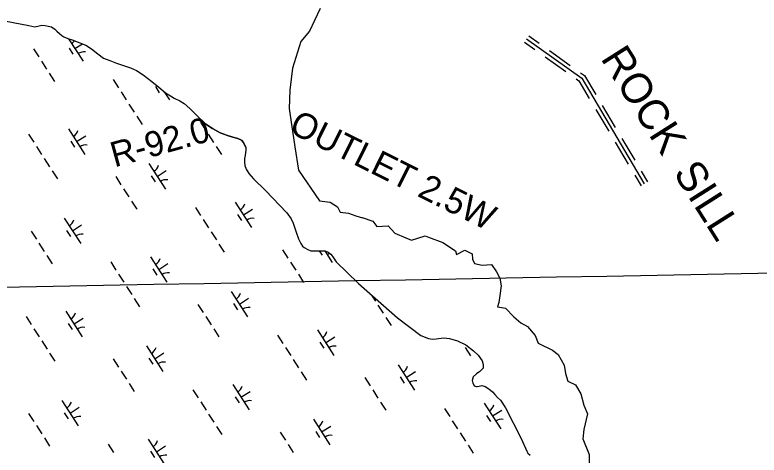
# Model space of a CAD drawing. Extents: x 3937982 to 3958556, y 219448 to 241894.
# Drawn here: x 3947179 to 3948409, y 230057 to 230784 of the extents above; entities that cross this region are included whole.
import ezdxf

# ---------------------------------------------------------------- set-up
doc = ezdxf.new("R2010")
doc.units = 0
for name, color, linetype in [('V-GRID-MAJR', 7, 'Continuous'), ('V-RIVR-EDGE', 7, 'Continuous'), ('V-RIVR-RANG-IDEN', 7, 'Continuous'), ('V-RRAP-DIKE', 7, 'Continuous'), ('V-RRAP-SILL-IDEN', 7, 'Continuous'), ('V-TOPO-SHOR', 7, 'Continuous'), ('V-WETL-SWMP', 7, 'Continuous')]:
    doc.layers.add(name, color=color, linetype=linetype)

msp = doc.modelspace()

# ---------------------------------------------------------------- linework, layer by layer
at = {"layer": 'V-GRID-MAJR'}
msp.add_spline([(3944087.88, 230278.368), (3946078.329, 230314.506), (3951399.696, 230411.652), (3955204.154, 230481.575)], degree=3, dxfattribs=at)
at = {"layer": 'V-RIVR-EDGE'}
for points in [[(3947683.499, 230794.294), (3947673.728, 230774.175), (3947665.68, 230756.931), (3947651.31, 230739.687), (3947637.514, 230695.426), (3947633.491, 230659.213), (3947632.341, 230628.748), (3947635.79, 230602.306), (3947641.538, 230565.518), (3947647.286, 230527.005), (3947682.062, 230476.709), (3947699.882, 230474.41), (3947711.953, 230466.363), (3947716.551, 230457.74), (3947730.347, 230456.016), (3947742.418, 230451.992), (3947753.196, 230448.687)], [(3947753.018, 230448.728), (3947770.118, 230443.028), (3947776.998, 230434.181), (3947795.673, 230435.164), (3947806.485, 230423.37), (3947825.16, 230415.506), (3947834.006, 230411.575), (3947856.613, 230418.455), (3947862.51, 230416.489), (3947886.1, 230407.643), (3947906.741, 230393.883), (3947908.706, 230387.985), (3947922.467, 230394.866), (3947934.262, 230388.968), (3947935.245, 230380.122), (3947938.193, 230373.242), (3947950.971, 230370.293), (3947966.697, 230371.276), (3947974.56, 230359.481), (3947980.458, 230348.67), (3947982.424, 230335.892), (3947980.458, 230320.166), (3947978.492, 230308.371), (3947976.526, 230301.491), (3947989.304, 230299.525), (3948003.064, 230284.781), (3948014.859, 230274.952), (3948025.671, 230269.055), (3948038.449, 230254.312), (3948043.363, 230241.534), (3948066.953, 230229.739), (3948076.782, 230222.859), (3948086.611, 230205.167), (3948088.576, 230191.406), (3948092.508, 230178.629), (3948105.286, 230172.731), (3948114.132, 230157.988), (3948119.046, 230139.313), (3948124.944, 230124.569), (3948119.046, 230099.014), (3948117.08, 230083.288), (3948127.892, 230057.732), (3948127.892, 230037.092)]]:
    msp.add_lwpolyline(points, dxfattribs=at)
at = {"layer": 'V-RRAP-DIKE'}
for points in [[(3948024.37, 230743.746), (3948115.495, 230678.973), (3948218.84, 230504.57)], [(3948027.991, 230748.84), (3948045.107, 230736.674)], [(3948020.749, 230738.652), (3948037.865, 230726.486)], [(3948062.223, 230724.507), (3948096.456, 230700.174)], [(3948054.981, 230714.319), (3948089.214, 230689.986)], [(3948113.572, 230688.008), (3948120.196, 230683.3), (3948138.816, 230651.878)], [(3948106.33, 230677.818), (3948110.794, 230674.646), (3948128.062, 230645.506)], [(3948149.521, 230633.812), (3948170.932, 230597.679)], [(3948138.767, 230627.44), (3948160.178, 230591.307)], [(3948170.883, 230573.241), (3948192.294, 230537.108)], [(3948181.637, 230579.613), (3948203.048, 230543.48)], [(3948213.754, 230525.414), (3948224.217, 230507.756)], [(3948203, 230519.042), (3948213.463, 230501.384)]]:
    msp.add_lwpolyline(points, dxfattribs=at)
at = {"layer": 'V-TOPO-SHOR'}
for p, q in [((3947139.6, 230778.041), (3947201.951, 230765.854)), ((3947201.951, 230765.854), (3947211.757, 230764.089)), ((3947219.203, 230765.329), (3947223.388, 230766.304)), ((3947223.388, 230766.304), (3947228.983, 230766.127)), ((3947228.983, 230766.127), (3947234.122, 230765.014)), ((3947211.757, 230764.089), (3947219.203, 230765.329)), ((3947234.122, 230765.014), (3947239.496, 230763.67)), ((3947239.496, 230763.67), (3947245.129, 230759.765)), ((3947245.129, 230759.765), (3947248.425, 230756.536)), ((3947248.425, 230756.536), (3947252.892, 230752.619)), ((3947252.892, 230752.619), (3947256.419, 230749.625)), ((3947256.419, 230749.625), (3947259.94, 230747.097)), ((3947259.94, 230747.097), (3947266.491, 230744.599)), ((3947266.491, 230744.599), (3947273.741, 230742.109)), ((3947273.741, 230742.109), (3947286.372, 230737.576)), ((3947286.372, 230737.576), (3947296.203, 230733.48)), ((3947296.203, 230733.48), (3947305.588, 230727.282)), ((3947305.588, 230727.282), (3947315.922, 230719.463)), ((3947315.922, 230719.463), (3947325.316, 230712.333)), ((3947325.316, 230712.333), (3947336.081, 230708.014)), ((3947336.081, 230708.014), (3947347.076, 230703.93)), ((3947347.076, 230703.93), (3947358.537, 230699.851)), ((3947358.537, 230699.851), (3947370.229, 230696.007)), ((3947370.229, 230696.007), (3947380.059, 230691.912)), ((3947380.059, 230691.912), (3947391.085, 230684.798)), ((3947391.085, 230684.798), (3947405.416, 230673.523)), ((3947405.416, 230673.523), (3947416.696, 230664.315)), ((3947416.696, 230664.315), (3947427.746, 230654.871)), ((3947427.746, 230654.871), (3947435.954, 230649.827)), ((3947435.954, 230649.827), (3947442.284, 230646.162)), ((3947442.284, 230646.162), (3947451.653, 230641.596)), ((3947451.653, 230641.596), (3947458.691, 230637.006))]:
    msp.add_line(p, q, dxfattribs=at)
msp.add_lwpolyline([(3947560.579, 230564.525), (3947556.759, 230572.973), (3947553.226, 230576.665), (3947547.371, 230579.403), (3947539.189, 230581.886), (3947530.307, 230584.36), (3947518.376, 230588.898), (3947505.488, 230595.761), (3947494.692, 230603.109), (3947486.224, 230610.947), (3947476.807, 230620.175), (3947468.095, 230628.943), (3947458.691, 230637.006)], dxfattribs=at)
at = {"layer": 'V-WETL-SWMP'}
for p, q in [((3947139.6, 230778.04), (3947201.951, 230765.853)), ((3947201.951, 230765.853), (3947211.757, 230764.088)), ((3947219.203, 230765.328), (3947223.388, 230766.303)), ((3947223.388, 230766.303), (3947228.983, 230766.126)), ((3947228.983, 230766.126), (3947234.122, 230765.013)), ((3947211.757, 230764.088), (3947219.203, 230765.328)), ((3947234.122, 230765.013), (3947239.496, 230763.669)), ((3947239.496, 230763.669), (3947245.129, 230759.764)), ((3947245.129, 230759.764), (3947248.425, 230756.535)), ((3947248.425, 230756.535), (3947252.892, 230752.618)), ((3947252.892, 230752.618), (3947256.419, 230749.624)), ((3947256.419, 230749.624), (3947259.94, 230747.096)), ((3947259.94, 230747.096), (3947266.491, 230744.598)), ((3947266.491, 230744.598), (3947273.741, 230742.108)), ((3947267.741, 230744.169), (3947291.721, 230706.914)), ((3947273.741, 230742.108), (3947286.372, 230737.575)), ((3947268.455, 230728.805), (3947274.95, 230718.714)), ((3947278.19, 230727.935), (3947290.497, 230735.857)), ((3947286.372, 230737.575), (3947296.203, 230733.479)), ((3947296.203, 230733.479), (3947305.588, 230727.281)), ((3947209.793, 230727.56), (3947218.453, 230714.106)), ((3947305.588, 230727.281), (3947315.922, 230719.462)), ((3947315.922, 230719.462), (3947325.316, 230712.332)), ((3947222.783, 230707.379), (3947231.443, 230693.925)), ((3947325.316, 230712.332), (3947336.081, 230708.013)), ((3947336.081, 230708.013), (3947347.076, 230703.929)), ((3947347.076, 230703.929), (3947358.537, 230699.85)), ((3947358.537, 230699.85), (3947370.229, 230696.006)), ((3947370.229, 230696.006), (3947380.059, 230691.911)), ((3947380.059, 230691.911), (3947391.085, 230684.797)), ((3947235.773, 230687.198), (3947244.433, 230673.745)), ((3947391.085, 230684.797), (3947405.416, 230673.522)), ((3947341.36, 230676.672), (3947350.02, 230663.218)), ((3947405.416, 230673.522), (3947416.696, 230664.314)), ((3947354.35, 230656.491), (3947363.01, 230643.037)), ((3947411.021, 230665.114), (3947417.516, 230655.024)), ((3947416.696, 230664.314), (3947427.746, 230654.87)), ((3947425.623, 230656.685), (3947434.287, 230643.224)), ((3947427.746, 230654.87), (3947435.954, 230649.826)), ((3947435.954, 230649.826), (3947442.284, 230646.161)), ((3947442.284, 230646.161), (3947451.653, 230641.595)), ((3947367.34, 230636.31), (3947376, 230622.857)), ((3947451.653, 230641.595), (3947458.691, 230637.005)), ((3947458.691, 230637.005), (3947468.095, 230628.943)), ((3947468.095, 230628.943), (3947476.807, 230620.175)), ((3947476.807, 230620.175), (3947486.223, 230610.947)), ((3947380.33, 230616.13), (3947388.99, 230602.676)), ((3947485.488, 230606.571), (3947494.148, 230593.117)), ((3947486.223, 230610.947), (3947494.693, 230603.109)), ((3947267.358, 230595.237), (3947294.42, 230553.194)), ((3947494.693, 230603.109), (3947505.488, 230595.76)), ((3947505.488, 230595.76), (3947518.376, 230588.899)), ((3947201.493, 230586.642), (3947210.153, 230573.188)), ((3947280.889, 230574.216), (3947296.024, 230583.958)), ((3947498.478, 230586.39), (3947507.138, 230572.937)), ((3947518.376, 230588.899), (3947530.308, 230584.359)), ((3947530.308, 230584.359), (3947539.189, 230581.885)), ((3947539.189, 230581.885), (3947547.371, 230579.404)), ((3947271.154, 230575.085), (3947277.649, 230564.994)), ((3947547.371, 230579.404), (3947553.226, 230576.666)), ((3947553.226, 230576.666), (3947556.759, 230572.973)), ((3947556.759, 230572.973), (3947560.579, 230564.524)), ((3947214.483, 230566.462), (3947223.143, 230553.008)), ((3947511.468, 230566.21), (3947520.128, 230552.756)), ((3947560.38, 230560.658), (3947559.306, 230551.557)), ((3947560.579, 230564.524), (3947560.38, 230560.658)), ((3947227.473, 230546.281), (3947236.133, 230532.827)), ((3947559.306, 230551.557), (3947558.424, 230546.654)), ((3947558.424, 230546.654), (3947558.48, 230541.061)), ((3947400.487, 230537.939), (3947427.549, 230495.895)), ((3947558.48, 230541.061), (3947559.008, 230535.007)), ((3947559.008, 230535.007), (3947560.933, 230528.967)), ((3947240.462, 230526.1), (3947249.122, 230512.646)), ((3947414.018, 230516.917), (3947429.154, 230526.659)), ((3947560.933, 230528.967), (3947565.434, 230521.787)), ((3947565.434, 230521.787), (3947573.217, 230512.777)), ((3947345.621, 230516.542), (3947354.281, 230503.088)), ((3947404.283, 230517.786), (3947410.778, 230507.696)), ((3947573.217, 230512.777), (3947592.99, 230493.4)), ((3947358.611, 230496.361), (3947367.271, 230482.907)), ((3947592.99, 230493.4), (3947628.321, 230456.701)), ((3947371.601, 230476.18), (3947380.261, 230462.726)), ((3947543.053, 230474.248), (3947570.115, 230432.205)), ((3947477.188, 230465.654), (3947485.848, 230452.2)), ((3947556.584, 230453.227), (3947571.72, 230462.969)), ((3947260.62, 230447.909), (3947287.682, 230405.866)), ((3947546.849, 230454.096), (3947553.344, 230444.006)), ((3947628.321, 230456.701), (3947635.183, 230446.515)), ((3947635.183, 230446.515), (3947638.747, 230439.793)), ((3947274.151, 230426.888), (3947289.286, 230436.63)), ((3947490.178, 230445.473), (3947498.838, 230432.019)), ((3947638.747, 230439.793), (3947643.794, 230424.695)), ((3947205.754, 230426.512), (3947214.414, 230413.058)), ((3947264.416, 230427.757), (3947270.911, 230417.666)), ((3947503.168, 230425.292), (3947511.828, 230411.838)), ((3947643.794, 230424.695), (3947647.398, 230414.01)), ((3947647.398, 230414.01), (3947651.44, 230406.127)), ((3947218.744, 230406.331), (3947227.404, 230392.878)), ((3947516.158, 230405.111), (3947524.818, 230391.658)), ((3947651.44, 230406.127), (3947654.281, 230401.728)), ((3947654.281, 230401.728), (3947657.103, 230399.193)), ((3947657.103, 230399.193), (3947662.729, 230395.987)), ((3947231.733, 230386.151), (3947240.393, 230372.697)), ((3947403.186, 230384.219), (3947430.248, 230342.176)), ((3947621.316, 230395.553), (3947629.976, 230382.099)), ((3947662.729, 230395.987), (3947668.108, 230394.177)), ((3947668.108, 230394.177), (3947676.034, 230394.024)), ((3947676.034, 230394.024), (3947684.19, 230394.106)), ((3947681.727, 230394.081), (3947686.473, 230386.707)), ((3947684.19, 230394.106), (3947691.649, 230393.949)), ((3947690.978, 230393.963), (3947703.244, 230374.907)), ((3947691.649, 230393.949), (3947696.798, 230391.903)), ((3947696.798, 230391.903), (3947701.03, 230388.217)), ((3947701.03, 230388.217), (3947704.333, 230384.289)), ((3947704.333, 230384.289), (3947709.547, 230375.718)), ((3947337.321, 230375.624), (3947345.981, 230362.17)), ((3947416.717, 230363.197), (3947431.852, 230372.94)), ((3947634.306, 230375.372), (3947642.966, 230361.918)), ((3947709.547, 230375.718), (3947746.502, 230339.735)), ((3947406.982, 230364.067), (3947413.477, 230353.976)), ((3947350.311, 230355.443), (3947358.97, 230341.989)), ((3947647.296, 230355.191), (3947655.956, 230341.738)), ((3947363.3, 230335.263), (3947371.96, 230321.809)), ((3947746.502, 230339.735), (3947811.163, 230283.522)), ((3947536.315, 230326.92), (3947563.377, 230284.877)), ((3947376.29, 230315.082), (3947384.95, 230301.628)), ((3947549.846, 230305.899), (3947564.982, 230315.641)), ((3947768.195, 230320.876), (3947774.533, 230311.03)), ((3947481.449, 230305.523), (3947490.109, 230292.07)), ((3947540.111, 230306.768), (3947546.606, 230296.678)), ((3947778.863, 230304.303), (3947787.523, 230290.849)), ((3947263.318, 230294.189), (3947290.381, 230252.146)), ((3947197.453, 230285.595), (3947206.113, 230272.141)), ((3947267.114, 230274.037), (3947273.609, 230263.947)), ((3947276.85, 230273.168), (3947291.985, 230282.91)), ((3947494.439, 230285.343), (3947503.099, 230271.889)), ((3947791.853, 230284.123), (3947800.513, 230270.669)), ((3947811.163, 230283.522), (3947849.914, 230254.315)), ((3947210.443, 230265.414), (3947219.103, 230251.96)), ((3947507.429, 230265.162), (3947516.089, 230251.708)), ((3947678.881, 230263.23), (3947705.943, 230221.187)), ((3947613.016, 230254.635), (3947621.676, 230241.181)), ((3947692.412, 230242.209), (3947707.547, 230251.951)), ((3947849.914, 230254.315), (3947862.319, 230249.081)), ((3947862.319, 230249.081), (3947869.086, 230248.217)), ((3947875.141, 230248.744), (3947887.009, 230250.496)), ((3947887.009, 230250.496), (3947897.044, 230249.199)), ((3947897.044, 230249.199), (3947910.134, 230245.369)), ((3947223.433, 230245.233), (3947232.093, 230231.779)), ((3947396.448, 230236.891), (3947423.51, 230194.848)), ((3947682.677, 230243.078), (3947689.172, 230232.987)), ((3947869.086, 230248.217), (3947875.141, 230248.744)), ((3947910.134, 230245.369), (3947924.182, 230238.986)), ((3947918.147, 230241.728), (3947918.661, 230240.93)), ((3947924.182, 230238.986), (3947936.868, 230229.093)), ((3947236.423, 230225.052), (3947245.083, 230211.598)), ((3947409.979, 230215.869), (3947425.114, 230225.612)), ((3947626.006, 230234.455), (3947634.666, 230221.001)), ((3947922.991, 230234.203), (3947931.651, 230220.749)), ((3947936.868, 230229.093), (3947944.636, 230221.48)), ((3947341.582, 230215.494), (3947350.241, 230202.04)), ((3947400.244, 230216.738), (3947406.739, 230206.648)), ((3947638.996, 230214.274), (3947647.655, 230200.82)), ((3947944.636, 230221.48), (3947951.02, 230212.455)), ((3947951.02, 230212.455), (3947952.713, 230206.413)), ((3947812.01, 230205.932), (3947839.072, 230163.888)), ((3947952.541, 230200.352), (3947947.24, 230194.471)), ((3947952.713, 230206.413), (3947952.541, 230200.352)), ((3947354.571, 230195.313), (3947363.231, 230181.859)), ((3947651.985, 230194.093), (3947660.645, 230180.639)), ((3947825.541, 230184.91), (3947840.677, 230194.652)), ((3947941.452, 230190.684), (3947936.139, 230185.969)), ((3947947.24, 230194.471), (3947941.452, 230190.684)), ((3947367.561, 230175.132), (3947376.221, 230161.679)), ((3947757.144, 230184.535), (3947765.804, 230171.081)), ((3947815.806, 230185.779), (3947822.301, 230175.689)), ((3947936.139, 230185.969), (3947934.572, 230179.66)), ((3947934.572, 230179.66), (3947935.549, 230175.242)), ((3947935.549, 230175.242), (3947937.914, 230171.77)), ((3947473.148, 230164.606), (3947481.808, 230151.152)), ((3947539.013, 230173.201), (3947566.076, 230131.158)), ((3947770.134, 230164.354), (3947778.794, 230150.9)), ((3947937.914, 230171.77), (3947939.557, 230170.621)), ((3947939.557, 230170.621), (3947941.429, 230169.941)), ((3947941.429, 230169.941), (3947942.829, 230169.722)), ((3947942.829, 230169.722), (3947946.082, 230170.687)), ((3947946.082, 230170.687), (3947950.501, 230171.664)), ((3947950.501, 230171.664), (3947955.879, 230169.854)), ((3947955.879, 230169.854), (3947962.209, 230166.189)), ((3947962.209, 230166.189), (3947967.854, 230161.119)), ((3947542.809, 230153.048), (3947549.304, 230142.958)), ((3947552.545, 230152.179), (3947567.68, 230161.922)), ((3947967.854, 230161.119), (3947972.094, 230156.734)), ((3947972.094, 230156.734), (3947976.571, 230151.885)), ((3947976.571, 230151.885), (3947981.279, 230147.271)), ((3947256.58, 230146.861), (3947283.643, 230104.818)), ((3947486.138, 230144.425), (3947494.798, 230130.971)), ((3947783.124, 230144.173), (3947791.784, 230130.719)), ((3947954.576, 230142.241), (3947981.638, 230100.198)), ((3947981.279, 230147.271), (3947989.562, 230134.77)), ((3947260.376, 230126.709), (3947266.871, 230116.619)), ((3947270.111, 230125.84), (3947285.247, 230135.582)), ((3947888.711, 230133.647), (3947897.371, 230120.193)), ((3947968.107, 230121.22), (3947983.243, 230130.962)), ((3947989.562, 230134.77), (3948015.247, 230083.989)), ((3947201.714, 230125.464), (3947210.374, 230112.01)), ((3947499.128, 230124.244), (3947507.788, 230110.79)), ((3947672.143, 230115.902), (3947699.205, 230073.859)), ((3947958.372, 230122.089), (3947964.867, 230111.999)), ((3947214.704, 230105.284), (3947223.364, 230091.83)), ((3947512.118, 230104.064), (3947520.778, 230090.61)), ((3947685.674, 230094.881), (3947700.809, 230104.623)), ((3947901.701, 230113.466), (3947910.361, 230100.012)), ((3947617.277, 230094.505), (3947625.937, 230081.051)), ((3947675.939, 230095.75), (3947682.434, 230085.659)), ((3947914.691, 230093.285), (3947923.351, 230079.831)), ((3947227.694, 230085.103), (3947236.354, 230071.649)), ((3947399.146, 230083.171), (3947426.209, 230041.128)), ((3948015.247, 230083.989), (3948024.783, 230062.877)), ((3947333.281, 230074.576), (3947341.941, 230061.122)), ((3947412.677, 230062.15), (3947427.813, 230071.892)), ((3947630.267, 230074.324), (3947638.926, 230060.871)), ((3947927.681, 230073.104), (3947936.341, 230059.65)), ((3947402.942, 230063.019), (3947409.437, 230052.928)), ((3948024.783, 230062.877), (3948026.676, 230060.1)), ((3948026.676, 230060.1), (3948030.207, 230056.64))]:
    msp.add_line(p, q, dxfattribs=at)
for centre, start, end in [((3947263.44, 230751.29), 301.99668, 323.224034), ((3947293.34, 230704.838), 81.996677, 123.540335), ((3947435.906, 230641.148), 122.557158, 123.540335), ((3947266.139, 230597.57), 301.99668, 343.540338), ((3947296.039, 230551.118), 81.996677, 123.540335), ((3947399.268, 230540.271), 301.99668, 343.540338), ((3947429.168, 230493.82), 81.996677, 123.540335), ((3947541.834, 230476.581), 301.99668, 343.540338), ((3947571.734, 230430.129), 81.996677, 123.540335), ((3947259.401, 230450.242), 301.99668, 343.540338), ((3947289.301, 230403.79), 81.996677, 123.540335), ((3947704.863, 230372.831), 107.913246, 123.540335), ((3947401.966, 230386.552), 301.99668, 343.540338), ((3947431.866, 230340.1), 81.996677, 123.540335), ((3947535.096, 230329.253), 301.99668, 343.540338), ((3947564.996, 230282.801), 81.996677, 123.540335), ((3947262.099, 230296.522), 301.99668, 343.540338), ((3947291.999, 230250.07), 81.996677, 123.540335), ((3947677.662, 230265.563), 301.99668, 343.540338), ((3947707.562, 230219.111), 81.996677, 123.540335), ((3947395.228, 230239.224), 301.99668, 343.540338), ((3947425.128, 230192.772), 81.996677, 123.540335), ((3947810.791, 230208.264), 301.99668, 343.540338), ((3947840.691, 230161.813), 81.996677, 123.540335), ((3947537.794, 230175.534), 301.99668, 343.540338), ((3947255.361, 230149.194), 301.99668, 343.540338), ((3947567.694, 230129.082), 81.996677, 123.540335), ((3947953.357, 230144.574), 301.99668, 343.540338), ((3947285.261, 230102.742), 81.996677, 123.540335), ((3947983.257, 230098.122), 81.996677, 123.540335), ((3947670.923, 230118.235), 301.99668, 343.540338), ((3947700.824, 230071.783), 81.996677, 123.540335), ((3947397.927, 230085.504), 301.99668, 343.540338), ((3947427.827, 230039.052), 81.996677, 123.540335)]:
    msp.add_arc(centre, 17.623, start, end, dxfattribs=at)

# ---------------------------------------------------------------- texts
at = {"layer": 'V-RIVR-RANG-IDEN'}
msp.add_text('R-92.0', height=41.5, rotation=15.372756, dxfattribs=at).set_placement((3947343.541, 230531.652))
at = {"layer": 'V-RRAP-SILL-IDEN'}
for s, height, rotation, p in [('ROCK', 49.9999, 302.315676, (3948145.805, 230711.806)), ('OUTLET 2.5W', 41.99992, 333.567412, (3947629.814, 230590.627)), ('SILL', 49.9999, 302.315676, (3948265.85, 230522.64))]:
    msp.add_text(s, height=height, rotation=rotation, dxfattribs=at).set_placement(p)

doc.saveas('drawing.dxf')
